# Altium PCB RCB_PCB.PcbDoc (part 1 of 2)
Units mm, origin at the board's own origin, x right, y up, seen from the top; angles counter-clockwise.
Board outline 360 x 80 mm, 2 copper layers (Top Layer, Bottom Layer); 41 components, 10 nets, 166 pads, 2592 vias.
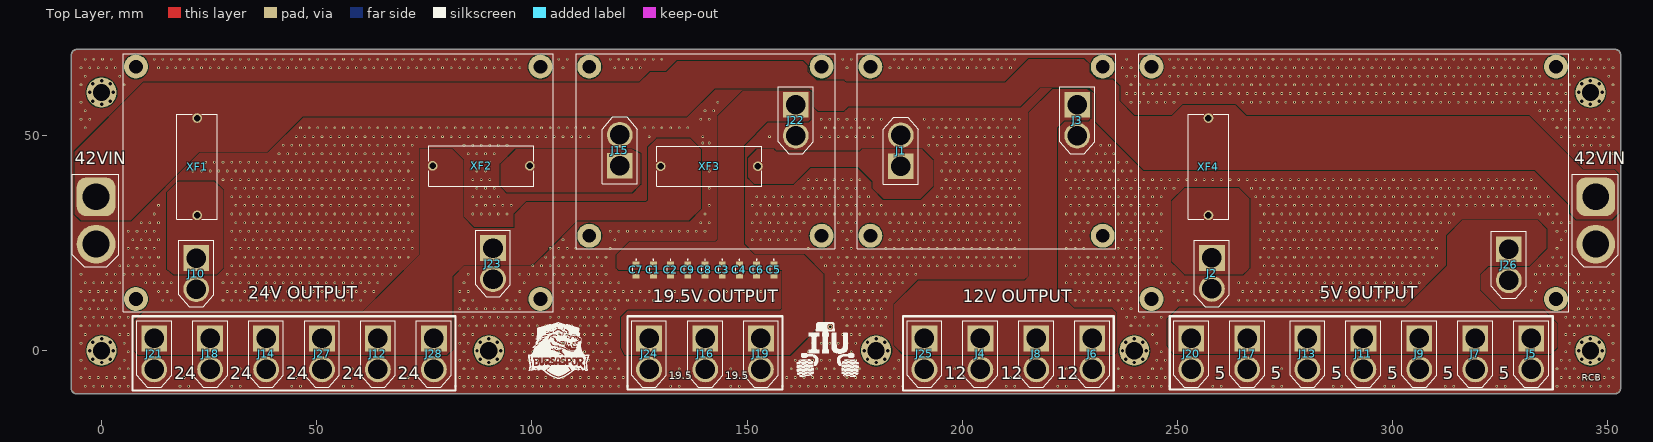
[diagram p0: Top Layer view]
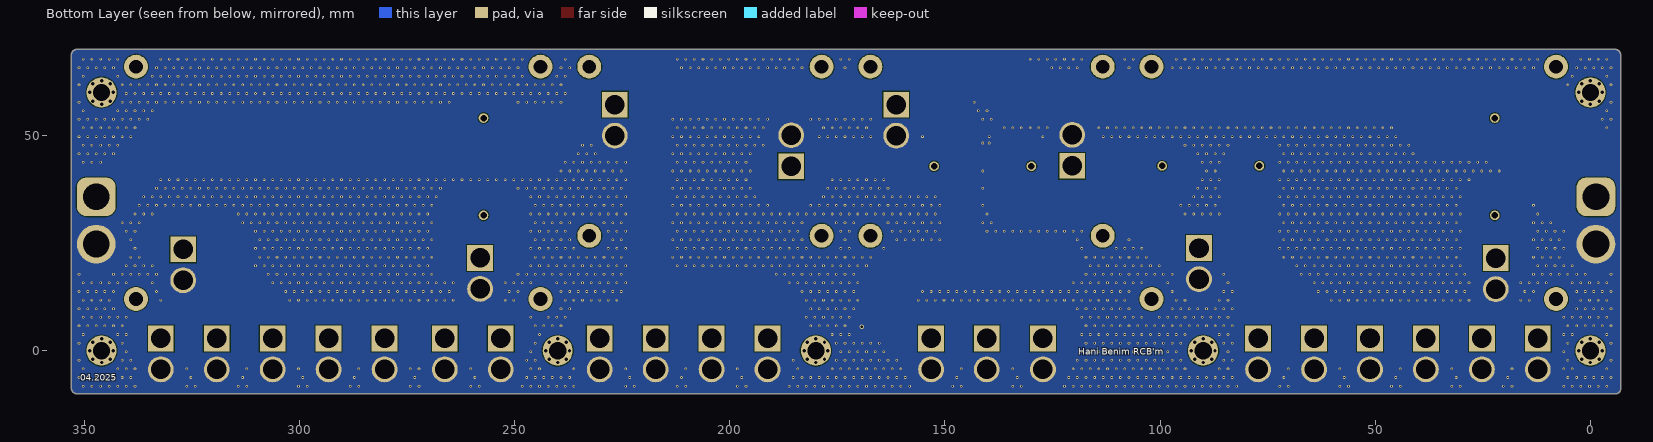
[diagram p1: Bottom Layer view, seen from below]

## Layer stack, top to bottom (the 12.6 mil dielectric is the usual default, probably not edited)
Top Solder: solder mask 0.0102, Solder Resist, Dk 3.5
Top Layer: signal copper 0.0356
Dielectric 1: dielectric 0.32, FR-4, Dk 4.8
Bottom Layer: signal copper 0.0356
Bottom Solder: solder mask 0.0102, Solder Resist, Dk 3.5

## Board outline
-7,-7.73 -7,68.73 cw(c-5.73,68.73) -5.73,70 351.73,70 cw(c351.73,68.73) 353,68.73 353,-8.73 cw(c351.73,-8.73) 351.73,-10 -5.941,-10 cw(c-5.941,-8.941) -7,-8.941

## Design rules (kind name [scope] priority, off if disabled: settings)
Clearance [All] p1: gap=0.2 ignorepadtopadclearanceinfootprint=FALSE
HoleSize [All] p1: absolutevalues=TRUE maxlimit=10 minlimit=0.3 maxpercent=80.000 minpercent=20.000
PolygonConnect [All] p1: connectstyle=Direct reliefconductorwidth=0.254 reliefentries=4 polygonreliefangle="90 Angle" airgapwidth=0.254
RoutingVias [All] p1: holewidth=0.711 width=1.27 viastyle="Through Hole" minholewidth=0.711 minwidth=1.27 maxholewidth=0.711 maxwidth=1.27
SilkToSilkClearance [All] p1: silktosilkclearance=0.05
SilkToSolderMaskClearance [IsPad] p1: minsilkscreentomaskgap=0.1 clearancetoexposedcopper=TRUE
SolderMaskExpansion [All] p1: expansion=0.102 istentingtop=FALSE
SupplyNets "Schematic Supply Nets" [InNet('GND')] p1: voltage=0.000
Width [All] p1: maxlimit=2 minlimit=0.25 preferedwidth=0.3 minimp=50.000000 maximp=50.000000 favimp=50.000000
27 further rules are at their usual default settings.

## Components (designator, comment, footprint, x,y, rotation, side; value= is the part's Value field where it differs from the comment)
C1 "GRM31CR61A107MEA8L" GRM31x 128.231,18.752 r270 top
C2 "GRM31CR61A107MEA8L" GRM31x 132.231,18.752 r270 top
C3 "GRM31CR61A107MEA8L" GRM31x 144.231,18.752 r270 top
C4 "GRM31CR61A107MEA8L" GRM31x 148.231,18.752 r270 top
C5 "GRM31CR61A107MEA8L" GRM31x 156.231,18.752 r270 top
C6 "GRM31CR61A107MEA8L" GRM31x 152.231,18.752 r270 top
C7 "GRM31CR61A107MEA8L" GRM31x 124.231,18.752 r270 top
C8 "GRM31CR61A107MEA8L" GRM31x 140.231,18.752 r270 top
C9 "GRM31CR61A107MEA8L" GRM31x 136.231,18.752 r270 top
J1 "XT60-M" XT60-M-Footprint-1 185.731,46.452 r90 top
J2 "XT60-M" XT60-M-Footprint-1 258.031,17.952 r270 top
J3 "XT60-M" XT60-M-Footprint-1 226.731,53.552 r270 top
J4 "XT60-M" XT60-M-Footprint-1 204.231,-0.75 r270 top
J5 "XT60-M" XT60-M-Footprint-1 332.231,-0.75 r270 top
J6 "XT60-M" XT60-M-Footprint-1 230.231,-0.75 r270 top
J7 "XT60-M" XT60-M-Footprint-1 319.231,-0.75 r270 top
J8 "XT60-M" XT60-M-Footprint-1 217.231,-0.75 r270 top
J9 "XT60-M" XT60-M-Footprint-1 306.231,-0.75 r270 top
J10 "XT60-M" XT60-M-Footprint-1 22,17.9 r270 top
J11 "XT60-M" XT60-M-Footprint-1 293.231,-0.75 r270 top
J12 "XT60-M" XT60-M-Footprint-1 64.231,-0.75 r270 top
J13 "XT60-M" XT60-M-Footprint-1 280.231,-0.75 r270 top
J14 "XT60-M" XT60-M-Footprint-1 38.231,-0.75 r270 top
J15 "XT60-M" XT60-M-Footprint-1 120.431,46.552 r90 top
J16 "XT60-M" XT60-M-Footprint-1 140.302,-0.75 r270 top
J17 "XT60-M" XT60-M-Footprint-1 266.231,-0.75 r270 top
J18 "XT60-M" XT60-M-Footprint-1 25.231,-0.75 r270 top
J19 "XT60-M" XT60-M-Footprint-1 153.231,-0.75 r270 top
J20 "XT60-M" XT60-M-Footprint-1 253.231,-0.75 r270 top
J21 "XT60-M" XT60-M-Footprint-1 12.231,-0.75 r270 top
J22 "XT60-M" XT60-M-Footprint-1 161.331,53.552 r270 top
J23 "XT60-M" XT60-M-Footprint-1 90.966,20.229 r270 top
J24 "XT60-M" XT60-M-Footprint-1 127.231,-0.75 r270 top
J25 "XT60-M" XT60-M-Footprint-1 191.231,-0.75 r270 top
J26 "XT60-M" XT60-M-Footprint-1 327.031,19.952 r270 top
J27 "XT60-M" XT60-M-Footprint-1 51.231,-0.75 r270 top
J28 "XT60-M" XT60-M-Footprint-1 77.231,-0.75 r270 top
XF1 "696108003002" 696108003002 22.231,42.752 r270 top
XF2 "696108003002" 696108003002 88.231,42.952 r0 top
XF3 "696108003002" 696108003002 141.231,42.852 r0 top
XF4 "696108003002" 696108003002 257.231,42.752 r270 top

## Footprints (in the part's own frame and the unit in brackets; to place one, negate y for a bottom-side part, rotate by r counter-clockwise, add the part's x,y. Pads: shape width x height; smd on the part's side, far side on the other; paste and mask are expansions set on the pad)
696108003002 [mm] "FUSEHOLDER BLOCKS - PCB - CLIP COVER - THT"
  round 2.25 hole 1.5: 1(-11.3,0) 2(11.3,0)
  silkscreen extent -12.2,-4.7 12.2,4.7, body extent -12.2,-4.7 12.2,4.7, height 11.55
GRM31x [mm]
  rect 1.05x1.6 smd: 1(-1.475,0) 2(1.475,0)
  silkscreen extent -2.5,-0.8 0.7,0.8, body extent -1.6,-0.8 1.6,0.8, height 1
XT60-M-Footprint-1 [mm]
  round 6 hole 4.55: N(3.6,0)
  rect 6x6 / inner round 6 / far side rect 6x6 hole 4.55: P(-3.6,0)
  silkscreen extent -7.75,-4.05 7.75,4.05, body extent -7.88,-3.92 7.62,4.18, height 16

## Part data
C1 C2 C3 C4 C5 C6 C7 C8 C9: "Capacitor", Manufacturer_Name="Murata Electronics", Mouser Part Number=81-GRM31CR61A107MA8L
J1 J2 J3 J4 J5 J6 J7 J8 J9 J10 J11 J12 J13 J14 J15 J16 J17 J18 J19 J20 J21 J22 J23 J24 J25 J26 J27 J28: library part CMP-002-00074-2, "XT60 Male Connector"
XF1 XF2 XF3 XF4: library part CMP-1502-00237-2, Fuse Current=10A, Voltage Rating (AC)=250V

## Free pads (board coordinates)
  round 0 hole 0.8: 3(0,-2.75) 3(0,57.25) 3(90,-2.75) 3(180,-2.75) 3(240,-2.75) 3(346,-2.75) 3(346,57.25) 4(2.75,0) 4(2.75,60) 4(92.75,0) 4(182.75,0) 4(242.75,0) 4(348.75,0) 4(348.75,60) 5(-2.75,0) 5(-2.75,60) 5(87.25,0) 5(177.25,0) 5(237.25,0) 5(343.25,0) 5(343.25,60) 6(0,2.75) 6(0,62.75) 6(90,2.75) 6(180,2.75) 6(240,2.75) 6(346,2.75) 6(346,62.75) 7(2,2) 7(2,62) 7(92,2) 7(182,2) 7(242,2) 7(348,2) 7(348,62) 8(-2,2) 8(-2,62) 8(88,2) 8(178,2) 8(238,2) 8(344,2) 8(344,62) 9(-2,-2) 9(-2,58) 9(88,-2) 9(178,-2) 9(238,-2) 9(344,-2) 9(344,58) 10(2,-2) 10(2,58) 10(92,-2) 10(182,-2) 10(242,-2) 10(348,-2) 10(348,58)
  round 1 hole 0.6: 12(169.331,5.552)
  round 9 hole 6.25: N(-1.269,24.752) N(347.231,24.752)
  rrect50% 9x9 hole 6.25: P(-1.269,35.752) P(347.231,35.752)
  round 7 hole 4 paste-2539.97: ""(0,0) ""(0,60) ""(90,0) ""(180,0) ""(240,0) ""(346,0) ""(346,60)
  round 5.55 hole 3.2 paste-2539.97: ""(8,12) ""(8,66) ""(102,12) ""(102,66) ""(113.333,26.7) ""(113.333,66) ""(167.333,26.7) ""(167.333,66) ""(178.663,26.7) ""(178.663,66) ""(232.663,26.7) ""(232.663,66) ""(243.993,12) ""(243.993,66) ""(337.993,12) ""(337.993,66)

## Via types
v1: diameter 0.6, hole 0.3, Top Layer to Bottom Layer, tented both sides, 2592 vias

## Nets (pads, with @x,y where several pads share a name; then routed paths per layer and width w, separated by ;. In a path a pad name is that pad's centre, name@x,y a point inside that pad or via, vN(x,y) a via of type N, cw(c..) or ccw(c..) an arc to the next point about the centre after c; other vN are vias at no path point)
5VIN: J2.P XF4.2
5VOUT: J5.P J7.P J9.P J11.P J13.P J17.P J20.P J26.P
12VIN: J1.P XF3.2
12VOUT: J3.P J4.P J6.P J8.P J25.P
19v5VIN: J15.P XF2.2
19v5VOUT: C1.1 C2.1 C3.1 C4.1 C5.1 C6.1 C7.1 C8.1 C9.1 J16.P J19.P J22.P J24.P
24VIN: J10.P XF1.2
24VOUT: J12.P J14.P J18.P J21.P J23.P J27.P J28.P XF2.1 XF3.1
42V_IN: pad.P XF1.1 XF4.1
